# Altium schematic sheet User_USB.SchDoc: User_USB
size A4; Date: Not used; ApprovedBy: Not used; CheckedBy: Not used; Author: Not used; CompanyName: STMicroelectronics; DrawnBy: Not used; Engineer: Not used; Organization: Not used; Address1: Not used; Address2: Not used; Address3: Not used; Address4: Not used; DocumentNumber: 7; Revision: Not used; SheetNumber: 7; SheetTotal: 8
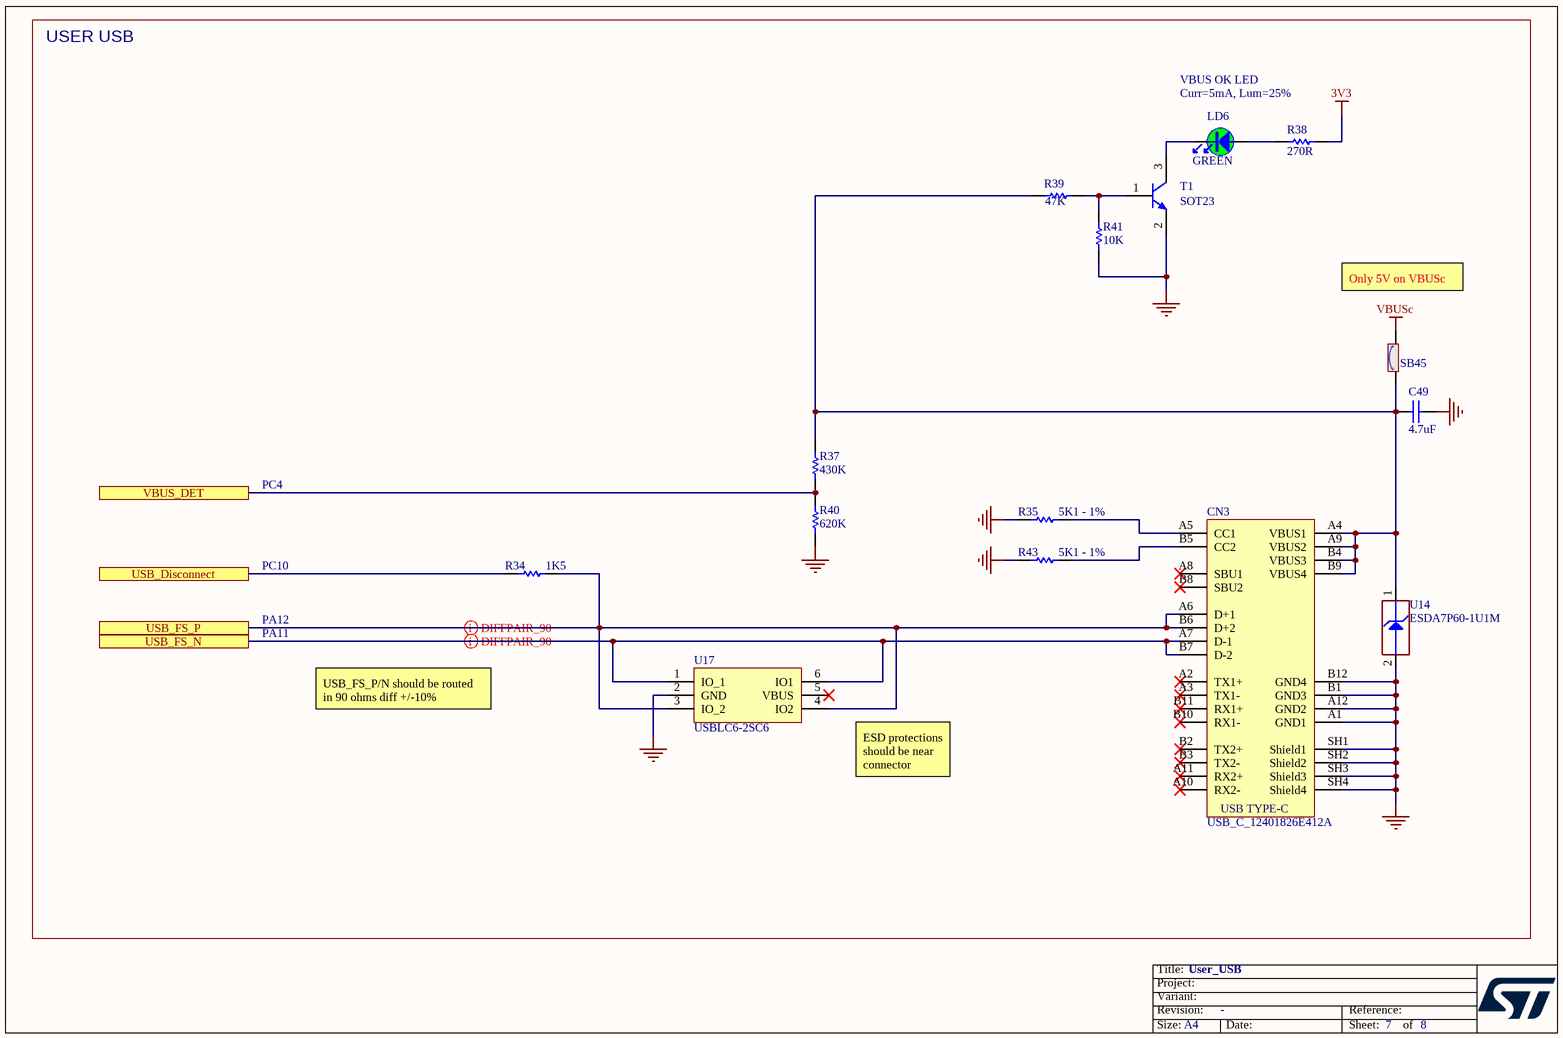
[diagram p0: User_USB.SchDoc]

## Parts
C49  value 4.7uF  [C0603]  (hidden comment: Capacitor)
CN3  value USB_C_12401826E412A  [CON_USB-TYPEC_AMPHENOL_12401826E412A]  (hidden comment: USB_TYPE_C_Receptacle)
LD6  value GREEN  [LED_0603_OSRAM_LG-Q396-PS-35_GREEN_1A2K_H0P4]  (hidden comment: LED_green)
R34  value 1K5  [R0603]  (hidden comment: Resistor)
R35  value 5K1 - 1%  [R0603]  (hidden comment: Resistor)
R37  value 430K  [R0603]  (hidden comment: Resistor)
R38  value 270R  [R0402]  (hidden comment: Resistor)
R39  value 47K  [R0402]  (hidden comment: Resistor)
R40  value 620K  [R0603]  (hidden comment: Resistor)
R41  value 10K  [R0402]  (hidden comment: Resistor)
R43  value 5K1 - 1%  [R0603]  (hidden comment: Resistor)
SB45  (no value)  [SOLDER-BRIDGE_R0603-0R]
T1  value SOT23  [NPN_SOT23]  (hidden comment: 9013-SOT23)
U14  value ESDA7P60-1U1M  [ESD_QFN2_1P6X1_P125]  (hidden comment: ESD-TRANSIL)
U17  USBLC6-2SC6  [ESD_SOT23-6L]

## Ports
USB_Disconnect, USB_FS_N, USB_FS_P, VBUS_DET

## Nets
3V3: R38.2
GND: C49.1 CN3.A1(GND1) CN3.A12(GND2) CN3.B1(GND3) CN3.B12(GND4) CN3.SH1(Shield1) CN3.SH2(Shield2) CN3.SH3(Shield3) CN3.SH4(Shield4) R35.1 R40.1 R41.1 R43.1 T1.2(E) U14.2(GND) U17.2(GND)
VBUSc: SB45.2
USB_Disconnect: R34.1 ; port USB_Disconnect
USB_FS_N: CN3.A7(D-1) CN3.B7(D-2) U17.1(IO_1) U17.6(IO1) ; port USB_FS_N
USB_FS_P: CN3.A6(D+1) CN3.B6(D+2) R34.2 U17.3(IO_2) U17.4(IO2) ; port USB_FS_P
VBUS_DET: R37.1 R40.2 ; port VBUS_DET
NetC49_2: C49.2 CN3.A4(VBUS1) CN3.A9(VBUS2) CN3.B4(VBUS3) CN3.B9(VBUS4) R37.2 R39.1 SB45.1 U14.1(IO1)
NetCN3_A5: CN3.A5(CC1) R35.2
NetCN3_B5: CN3.B5(CC2) R43.2
NetLD6_1: LD6.1 R38.1
NetLD6_2: LD6.2 T1.3(C)
NetR39_2: R39.2 R41.2 T1.1(B)

Not connected (* = marked no-connect by the designer): CN3 A2(TX1+)* A3(TX1-)* A8(SBU1)* A10(RX2-)* A11(RX2+)* B2(TX2+)* B3(TX2-)* B8(SBU2)* B10(RX1-)* B11(RX1+)*; U17 5(VBUS)*

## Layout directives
differential pair: USB_FS_N, USB_FS_P

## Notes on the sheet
- USER USB
- VBUS OK LED
- Curr=5mA, Lum=25%
- Only 5V on VBUSc
- PC4
- PC10
- PA11
- PA12
- USB_FS_P/N should be routed in 90 ohms diff +/-10%
- ESD protections should be near connector

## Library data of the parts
C49 = MCD-00009: Capacitor, MLCC, 4.7uF, 16V, X5R, 10%, 0603, T=0.8mm; Manufacturer_Part_Number: CC0603KRX5R7BB475; Manufacturer: YAGEO; Provided_By: SUBCO; ECCN_US: EAR99; ECCN_EU: NEC
CN3 = MCD-03232: USB_TypeC, 24 pins, RA, SMD, T=2.96mm; Part_Type: Connector; Part_Preference: Recommended; Manufacturer: AMPHENOL ICC; Manufacturer_Part_Number: 12401826E412A; Component_Country_Of_Origin: China°; ShowFields: YES; ID: 5348
LD6 = MCD-00588: LED Green, 0603 SMD, Forward Voltage Typ=2V, Max=2.5V; Part_Type: Display; Manufacturer_Part_Number: LG Q396-PS-35; Manufacturer: OSRAM OPTO SEMICONDUCTORS; Alternate_Manufacturer_Part_Number: VLMTG1300-GS08; Alternate_Manufacturer: VISHAY SEMICONDUCTOR OPTO DIVISION; Provided_By: SUBCO
R34 = MCD-00217: Resistor, 1K5, 0603, +/-1%, 1/10W; BMS_Part_Number: 9129766; Part_Preference: Recommended; Manufacturer: YAGEO; Manufacturer_Part_Number: RC0603FR-071K5L; Component_Country_Of_Origin: China; ShowFields: YES; ID: 2651
R35 R43 = MCD-00334: Resistor, 5K1, 0603, +/-1%, 1/10W; Part_Preference: Recommended; Manufacturer: YAGEO; Manufacturer_Part_Number: RC0603FR-075K1L
R37 = MCD-00480: Resistor, 430K, 0603, +/-1%, 1/10W; Part_Preference: Recommended; Manufacturer: YAGEO; Manufacturer_Part_Number: RC0603FR-07430KL; Component_Country_Of_Origin: China; ShowFields: YES; ID: 2798
R38 = MCD-00441: Resistor,270R,0402,1%,1/16W; Manufacturer_Part_Number: RC0402FR-07270RL; Manufacturer: YAGEO; Provided_By: SUBCO; ECCN_US: EAR99; ECCN_EU: NEC
R39 = MCD-00063: Resistor,47K,0402,1%,1/16W; Manufacturer_Part_Number: RC0402FR-0747KL; Manufacturer: YAGEO; Provided_By: SUBCO; ECCN_US: EAR99; ECCN_EU: NEC
R40 = MCD-00506: Resistor, 620K, 0603, +/-1%, 1/10W; Part_Preference: Recommended; Manufacturer: YAGEO; Manufacturer_Part_Number: RC0603FR-07620KL; Component_Country_Of_Origin: China; ShowFields: YES; ID: 3237
R41 = MCD-00053: Resistor,10K,0402,1%,1/16W; Manufacturer_Part_Number: RC0402FR-0710KL; Manufacturer: YAGEO; Provided_By: SUBCO; ECCN_US: EAR99; ECCN_EU: NEC
SB45 = MCD-00071: Solder Bridge ON; Part_Type: Mechanical; Manufacturer_Part_Number: RC0603JR-070RL; Manufacturer: YAGEO; Provided_By: SUBCO
T1 = MCD-00073: NPN Bipolar Transistor; Manufacturer_Part_Number: BSR14; Manufacturer: ON SEMICONDUCTOR; Part_Type: IC; Alternate_Manufacturer_Part_Number: MMBT2222ALT1G / MMBT2222ALT3G; Provided_By: SUBCO; ECCN_US: EAR99; ECCN_EU: NEC
U14 = MCD-00251: High power transient voltage suppressor, 7V breakdown; BMS_Part_Number: 9179042; Part_Type: Diode; Part_Preference: Recommended; Manufacturer: STMICROELECTRONICS; Manufacturer_HQ_COO: EU
U17 = MCD-00163: Very low capacitance ESD protection; Part_Type: IC; Manufacturer: STMICROELECTRONICS; BMS_Part_Number: 9151075; Provided_By: SUBCO with ST control; ECCN_US: EAR99; ECCN_EU: NEC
